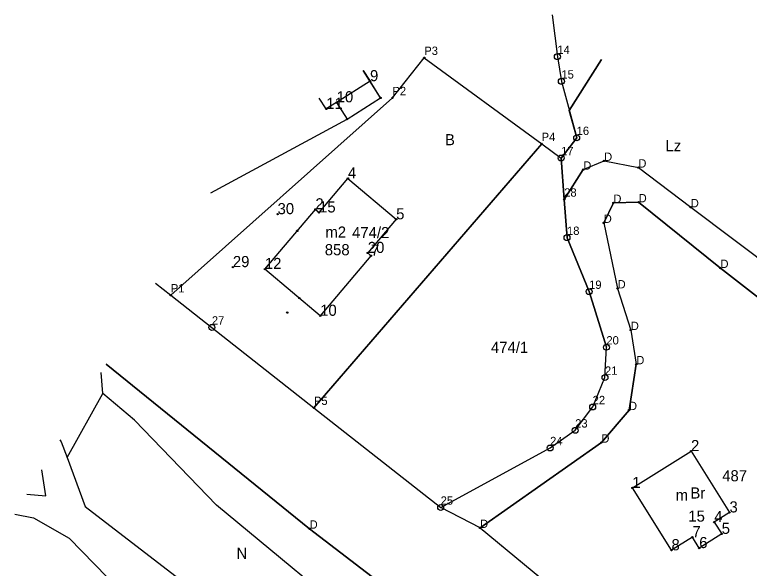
# Model space of a CAD drawing. Extents: x 7465393 to 7466459, y 5491258 to 5492404.
# Drawn here: x 7465422.8 to 7465521.9, y 5492329.6 to 5492404.3 of the extents above; entities that cross this region are included whole.
import ezdxf

# ---------------------------------------------------------------- set-up
doc = ezdxf.new("R2010")
doc.units = 0
for name, color, linetype in [('202-punkt graniczny', 7, 'Continuous'), ('202-punkt graniczny-Atr103', 7, 'Continuous'), ('203-punkt graniczny', 7, 'Continuous'), ('203-punkt graniczny-Atr103', 7, 'Continuous'), ('210-oznaczenie konturu użytku gruntowego', 7, 'Continuous'), ('211-numer działki ewidencyjnej', 7, 'Continuous'), ('217-kontur klasyfikacyjny', 7, 'Continuous'), ('218-kontur użytku gruntowego', 7, 'Continuous'), ('219-działka ewidencyjna', 7, 'Continuous'), ('312-budynek ewidencyjny', 7, 'Continuous'), ('312-oznaczenie budynku ewidencyjnego', 7, 'Continuous'), ('312-oznaczenie budynku ewidencyjnego-Atr117', 7, 'Continuous'), ('inny obiekt trwale związany z budynkiem (powierzchnia)', 7, 'Continuous'), ('Punkt budynku', 7, 'Continuous'), ('Punkt budynku-Atr103', 7, 'Continuous'), ('Punkt budynku-Atr104', 7, 'Continuous')]:
    doc.layers.add(name, color=color, linetype=linetype)

# ---------------------------------------------------------------- blocks, each defined once
blk = doc.blocks.new('203')
blk.add_circle((0, 0), 0.09)
blk = doc.blocks.new('202')
blk.add_circle((0, 0), 0.4)
blk = doc.blocks.new('PUNKTBUD')
blk.add_circle((0, 0), 0.09)

msp = doc.modelspace()

# ---------------------------------------------------------------- linework, layer by layer
at = {"layer": '217-kontur klasyfikacyjny'}
for points in [[(7465473.77, 5492393.05), (7465478.06, 5492398.48)], [(7465478.06, 5492398.48), (7465493.89, 5492386.86)], [(7465497.62, 5492391.35), (7465501.953, 5492398.257)], [(7465443.87, 5492366.44), (7465473.77, 5492393.05)], [(7465498.61, 5492387.68), (7465497.62, 5492391.35)], [(7465496.51, 5492384.95), (7465498.61, 5492387.68)], [(7465493.89, 5492386.86), (7465463.18, 5492351.26)], [(7465496.93, 5492379.36), (7465496.51, 5492384.95)], [(7465497.31, 5492374.2), (7465496.93, 5492379.36)], [(7465503.56, 5492378.89), (7465502.26, 5492376.2)], [(7465506.97, 5492378.97), (7465503.56, 5492378.89)], [(7465518, 5492370.11), (7465506.97, 5492378.97)], [(7465502.26, 5492376.2), (7465504.13, 5492367.35)], [(7465500.29, 5492366.92), (7465497.31, 5492374.2)], [(7465529.32, 5492361.27), (7465518, 5492370.11)], [(7465441.821, 5492368.048), (7465443.87, 5492366.44)], [(7465504.13, 5492367.35), (7465505.91, 5492361.74)], [(7465502.62, 5492359.42), (7465500.29, 5492366.92)], [(7465505.91, 5492361.74), (7465506.65, 5492357.12)], [(7465502.43, 5492355.33), (7465502.62, 5492359.42)], [(7465506.65, 5492357.12), (7465505.67, 5492350.94)], [(7465500.77, 5492351.36), (7465502.43, 5492355.33)], [(7465498.41, 5492348.21), (7465500.77, 5492351.36)], [(7465463.18, 5492351.26), (7465480.27, 5492337.8)], [(7465505.67, 5492350.94), (7465501.94, 5492346.55)], [(7465495.03, 5492345.83), (7465498.41, 5492348.21)], [(7465501.94, 5492346.55), (7465485.58, 5492335.04)], [(7465480.27, 5492337.8), (7465495.03, 5492345.83)], [(7465485.58, 5492335.04), (7465523.76, 5492303.5)]]:
    msp.add_lwpolyline(points, dxfattribs=at)
at = {"layer": '218-kontur użytku gruntowego'}
for points in [[(7465473.77, 5492393.05), (7465478.06, 5492398.48)], [(7465478.06, 5492398.48), (7465493.89, 5492386.86)], [(7465501.953, 5492398.257), (7465497.62, 5492391.35)], [(7465472.17, 5492393.07), (7465469.822, 5492396.777)], [(7465443.87, 5492366.44), (7465473.77, 5492393.05)], [(7465467.66, 5492390.21), (7465472.17, 5492393.07)], [(7465497.62, 5492391.35), (7465498.61, 5492387.68)], [(7465449.254, 5492380.23), (7465467.66, 5492390.21)], [(7465498.61, 5492387.68), (7465496.51, 5492384.95)], [(7465493.89, 5492386.86), (7465463.18, 5492351.26)], [(7465496.51, 5492384.95), (7465496.93, 5492379.36)], [(7465499.5, 5492383.38), (7465502.31, 5492384.56)], [(7465502.31, 5492384.56), (7465506.93, 5492383.66)], [(7465496.93, 5492379.36), (7465499.5, 5492383.38)], [(7465506.93, 5492383.66), (7465514, 5492378.3)], [(7465497.31, 5492374.2), (7465496.93, 5492379.36)], [(7465503.56, 5492378.89), (7465502.26, 5492376.2)], [(7465506.97, 5492378.97), (7465503.56, 5492378.89)], [(7465518, 5492370.11), (7465506.97, 5492378.97)], [(7465514, 5492378.3), (7465525.79, 5492369.48)], [(7465502.26, 5492376.2), (7465504.13, 5492367.35)], [(7465500.29, 5492366.92), (7465497.31, 5492374.2)], [(7465529.32, 5492361.27), (7465518, 5492370.11)], [(7465441.821, 5492368.048), (7465443.87, 5492366.44)], [(7465504.13, 5492367.35), (7465505.91, 5492361.74)], [(7465443.87, 5492366.44), (7465449.41, 5492362.1)], [(7465502.62, 5492359.42), (7465500.29, 5492366.92)], [(7465449.41, 5492362.1), (7465463.18, 5492351.26)], [(7465505.91, 5492361.74), (7465506.65, 5492357.12)], [(7465502.43, 5492355.33), (7465502.62, 5492359.42)], [(7465462.59, 5492334.94), (7465435.166, 5492357.141)], [(7465506.65, 5492357.12), (7465505.67, 5492350.94)], [(7465434.71, 5492353.16), (7465434.482, 5492356.021)], [(7465500.77, 5492351.36), (7465502.43, 5492355.33)], [(7465429.89, 5492344.53), (7465434.71, 5492353.16)], [(7465438.97, 5492349.58), (7465434.71, 5492353.16)], [(7465498.41, 5492348.21), (7465500.77, 5492351.36)], [(7465463.18, 5492351.26), (7465480.27, 5492337.8)], [(7465505.67, 5492350.94), (7465501.94, 5492346.55)], [(7465450.05, 5492338.11), (7465438.97, 5492349.58)], [(7465495.03, 5492345.83), (7465498.41, 5492348.21)], [(7465428.926, 5492346.915), (7465429.1, 5492346.66)], [(7465429.1, 5492346.66), (7465429.89, 5492344.53)], [(7465501.94, 5492346.55), (7465485.58, 5492335.04)], [(7465480.27, 5492337.8), (7465495.03, 5492345.83)], [(7465506.12, 5492340.43), (7465514.03, 5492345.4)], [(7465514.03, 5492345.4), (7465519.22, 5492337.13)], [(7465429.89, 5492344.53), (7465432.33, 5492337.92)], [(7465427.02, 5492339.39), (7465426.465, 5492342.882)], [(7465424.47, 5492339.612), (7465427.02, 5492339.39)], [(7465511.4, 5492332.03), (7465506.12, 5492340.43)], [(7465432.33, 5492337.92), (7465445.57, 5492327.74)], [(7465471.73, 5492320.14), (7465450.05, 5492338.11)], [(7465422.817, 5492336.903), (7465425.34, 5492336.41)], [(7465519.22, 5492337.13), (7465517.16, 5492335.83)], [(7465425.34, 5492336.41), (7465430.17, 5492333.65)], [(7465517.16, 5492335.83), (7465518.17, 5492334.24)], [(7465494.69, 5492310.3), (7465462.59, 5492334.94)], [(7465485.58, 5492335.04), (7465501.21, 5492322.13)], [(7465430.17, 5492333.65), (7465442.09, 5492321.44)], [(7465514.22, 5492333.79), (7465511.4, 5492332.03)], [(7465515.14, 5492332.32), (7465514.22, 5492333.79)], [(7465518.17, 5492334.24), (7465515.14, 5492332.32)]]:
    msp.add_lwpolyline(points, dxfattribs=at)
at = {"layer": '219-działka ewidencyjna'}
for points in [[(7465495.284, 5492404.286), (7465496.01, 5492398.62)], [(7465473.77, 5492393.05), (7465478.06, 5492398.48)], [(7465478.06, 5492398.48), (7465493.89, 5492386.86)], [(7465496.01, 5492398.62), (7465496.55, 5492395.29)], [(7465496.55, 5492395.29), (7465498.61, 5492387.68)], [(7465443.87, 5492366.44), (7465473.77, 5492393.05)], [(7465496.51, 5492384.95), (7465498.61, 5492387.68)], [(7465463.18, 5492351.26), (7465493.89, 5492386.86)], [(7465493.89, 5492386.86), (7465496.51, 5492384.95)], [(7465496.51, 5492384.95), (7465496.93, 5492379.36)], [(7465499.5, 5492383.38), (7465502.31, 5492384.56)], [(7465502.31, 5492384.56), (7465506.93, 5492383.66)], [(7465499.5, 5492383.38), (7465496.93, 5492379.36)], [(7465506.93, 5492383.66), (7465514, 5492378.3)], [(7465496.93, 5492379.36), (7465497.31, 5492374.2)], [(7465502.26, 5492376.2), (7465503.56, 5492378.89)], [(7465503.56, 5492378.89), (7465506.97, 5492378.97)], [(7465506.97, 5492378.97), (7465518, 5492370.11)], [(7465514, 5492378.3), (7465525.79, 5492369.48)], [(7465502.26, 5492376.2), (7465504.13, 5492367.35)], [(7465497.31, 5492374.2), (7465500.29, 5492366.92)], [(7465518, 5492370.11), (7465529.32, 5492361.27)], [(7465441.821, 5492368.048), (7465443.87, 5492366.44)], [(7465504.13, 5492367.35), (7465505.91, 5492361.74)], [(7465443.87, 5492366.44), (7465449.41, 5492362.1)], [(7465500.29, 5492366.92), (7465502.62, 5492359.42)], [(7465449.41, 5492362.1), (7465463.18, 5492351.26)], [(7465505.91, 5492361.74), (7465506.65, 5492357.12)], [(7465502.43, 5492355.33), (7465502.62, 5492359.42)], [(7465435.167, 5492357.143), (7465462.59, 5492334.94)], [(7465505.67, 5492350.94), (7465506.65, 5492357.12)], [(7465500.77, 5492351.36), (7465502.43, 5492355.33)], [(7465498.41, 5492348.21), (7465500.77, 5492351.36)], [(7465463.18, 5492351.26), (7465480.27, 5492337.8)], [(7465501.94, 5492346.55), (7465505.67, 5492350.94)], [(7465495.03, 5492345.83), (7465498.41, 5492348.21)], [(7465485.58, 5492335.04), (7465501.94, 5492346.55)], [(7465480.27, 5492337.8), (7465495.03, 5492345.83)], [(7465485.58, 5492335.04), (7465480.27, 5492337.8)], [(7465462.59, 5492334.94), (7465494.69, 5492310.3)], [(7465485.58, 5492335.04), (7465523.76, 5492303.5)]]:
    msp.add_lwpolyline(points, dxfattribs=at)
at = {"layer": '312-budynek ewidencyjny'}
for points in [[(7465469.818, 5492396.775), (7465470.74, 5492395.31)], [(7465470.74, 5492395.31), (7465466.24, 5492392.46)], [(7465464.83, 5492391.57), (7465463.9, 5492393.039)], [(7465466.24, 5492392.46), (7465464.83, 5492391.57)], [(7465463.87, 5492377.6), (7465467.76, 5492382.2)], [(7465467.76, 5492382.2), (7465474.27, 5492376.68)], [(7465456.56, 5492369.97), (7465463.37, 5492378.02)], [(7465463.37, 5492378.02), (7465463.87, 5492377.6)], [(7465474.27, 5492376.68), (7465470.44, 5492372.14)], [(7465470.44, 5492372.14), (7465470.87, 5492371.77)], [(7465470.87, 5492371.77), (7465464.02, 5492363.66)], [(7465464.02, 5492363.66), (7465456.56, 5492369.97)], [(7465506.12, 5492340.43), (7465514.03, 5492345.4)], [(7465514.03, 5492345.4), (7465519.22, 5492337.13)], [(7465511.4, 5492332.03), (7465506.12, 5492340.43)], [(7465519.22, 5492337.13), (7465517.16, 5492335.83)], [(7465517.16, 5492335.83), (7465518.17, 5492334.24)], [(7465514.22, 5492333.79), (7465511.4, 5492332.03)], [(7465515.14, 5492332.32), (7465514.22, 5492333.79)], [(7465518.17, 5492334.24), (7465515.14, 5492332.32)]]:
    msp.add_lwpolyline(points, dxfattribs=at)
at = {"layer": 'inny obiekt trwale związany z budynkiem (powierzchnia)'}
msp.add_lwpolyline([(7465470.74, 5492395.31), (7465466.24, 5492392.46), (7465467.66, 5492390.21), (7465472.16, 5492393.06)], close=True, dxfattribs=at)

# ---------------------------------------------------------------- block references
at = {"layer": '202-punkt graniczny'}
for p in [(7465496.01, 5492398.62), (7465496.55, 5492395.29), (7465498.61, 5492387.68), (7465496.51, 5492384.95), (7465497.31, 5492374.2), (7465500.29, 5492366.92), (7465449.41, 5492362.1), (7465502.62, 5492359.42), (7465502.43, 5492355.33), (7465500.77, 5492351.36), (7465498.41, 5492348.21), (7465495.03, 5492345.83), (7465480.27, 5492337.8)]:
    msp.add_blockref('202', p, dxfattribs=at)
at = {"layer": '203-punkt graniczny'}
for p in [(7465478.06, 5492398.48), (7465473.77, 5492393.05), (7465493.89, 5492386.86), (7465502.31, 5492384.56), (7465499.5, 5492383.38), (7465506.93, 5492383.66), (7465496.93, 5492379.36), (7465503.56, 5492378.89), (7465506.97, 5492378.97), (7465514, 5492378.3), (7465502.26, 5492376.2), (7465518, 5492370.11), (7465504.13, 5492367.35), (7465443.87, 5492366.44), (7465505.91, 5492361.74), (7465506.65, 5492357.12), (7465463.18, 5492351.26), (7465505.67, 5492350.94), (7465501.94, 5492346.55), (7465462.59, 5492334.94), (7465485.58, 5492335.04)]:
    msp.add_blockref('203', p, dxfattribs=at)
at = {"layer": 'Punkt budynku'}
for p in [(7465470.74, 5492395.31), (7465472.16, 5492393.06), (7465466.24, 5492392.46), (7465464.83, 5492391.57), (7465467.66, 5492390.21), (7465467.76, 5492382.2), (7465463.37, 5492378.02), (7465458.27, 5492377.37), (7465463.87, 5492377.6), (7465474.27, 5492376.68), (7465460.92, 5492375.12), (7465470.44, 5492372.14), (7465470.87, 5492371.77), (7465452.24, 5492370.23), (7465456.56, 5492369.97), (7465461.21, 5492366.04), (7465459.57, 5492364.1), (7465464.02, 5492363.66), (7465514.03, 5492345.4), (7465506.12, 5492340.43), (7465519.22, 5492337.13), (7465517.16, 5492335.83), (7465514.22, 5492333.79), (7465518.17, 5492334.24), (7465511.4, 5492332.03), (7465515.14, 5492332.32)]:
    msp.add_blockref('PUNKTBUD', p, dxfattribs=at)

# ---------------------------------------------------------------- texts
at = {"layer": '202-punkt graniczny-Atr103'}
for s, p in [('14', (7465496.01, 5492398.995)), ('15', (7465496.55, 5492395.665)), ('16', (7465498.61, 5492388.055)), ('17', (7465496.51, 5492385.325)), ('18', (7465497.31, 5492374.575)), ('19', (7465500.29, 5492367.295)), ('27', (7465449.41, 5492362.475)), ('20', (7465502.62, 5492359.795)), ('21', (7465502.43, 5492355.705)), ('22', (7465500.77, 5492351.735)), ('23', (7465498.41, 5492348.585)), ('24', (7465495.03, 5492346.205)), ('25', (7465480.27, 5492338.175))]:
    msp.add_text(s, height=1.125, dxfattribs=at).set_placement(p)
at = {"layer": '203-punkt graniczny-Atr103'}
for s, p in [('P3', (7465478.06, 5492398.855)), ('P2', (7465473.77, 5492393.425)), ('P4', (7465493.89, 5492387.235)), ('D', (7465502.31, 5492384.56)), ('D', (7465499.5, 5492383.38)), ('D', (7465506.93, 5492383.66)), ('28', (7465496.93, 5492379.735)), ('D', (7465506.97, 5492378.97)), ('D', (7465503.56, 5492378.89)), ('D', (7465514, 5492378.3)), ('D', (7465502.26, 5492376.2)), ('D', (7465518, 5492370.11)), ('D', (7465504.13, 5492367.35)), ('P1', (7465443.87, 5492366.815)), ('D', (7465505.91, 5492361.74)), ('D', (7465506.65, 5492357.12)), ('P5', (7465463.18, 5492351.635)), ('D', (7465505.67, 5492350.94)), ('D', (7465501.94, 5492346.55)), ('D', (7465462.59, 5492334.94)), ('D', (7465485.58, 5492335.04))]:
    msp.add_text(s, height=1.125, dxfattribs=at).set_placement(p)
at = {"layer": '210-oznaczenie konturu użytku gruntowego'}
for s, p in [('B', (7465480.85, 5492386.67)), ('Lz', (7465510.59, 5492385.87)), ('Br', (7465513.95, 5492339.01)), ('N', (7465452.73, 5492330.86))]:
    msp.add_text(s, height=1.5, dxfattribs=at).set_placement(p)
at = {"layer": '211-numer działki ewidencyjnej'}
for s, p in [('474/2', (7465468.32, 5492374.14)), ('474/1', (7465487.05, 5492358.65)), ('487', (7465518.24, 5492341.33))]:
    msp.add_text(s, height=1.5, dxfattribs=at).set_placement(p)
at = {"layer": '312-oznaczenie budynku ewidencyjnego'}
for s, p in [('858', (7465464.64, 5492371.83)), ('15', (7465513.67, 5492335.89))]:
    msp.add_text(s, height=1.5, dxfattribs=at).set_placement(p)
at = {"layer": '312-oznaczenie budynku ewidencyjnego-Atr117'}
for s, p in [('m2', (7465464.726, 5492374.21)), ('m', (7465511.963, 5492338.72))]:
    msp.add_text(s, height=1.5, dxfattribs=at).set_placement(p)
at = {"layer": 'Punkt budynku-Atr103'}
for s, p in [('15', (7465463.87, 5492377.6)), ('20', (7465470.44, 5492372.14)), ('12', (7465456.56, 5492369.97)), ('10', (7465464.02, 5492363.66))]:
    msp.add_text(s, height=1.5, dxfattribs=at).set_placement(p)
at = {"layer": 'Punkt budynku-Atr104'}
for s, p in [('9', (7465470.74, 5492395.31)), ('10', (7465466.24, 5492392.46)), ('11', (7465464.83, 5492391.57)), ('4', (7465467.76, 5492382.2)), ('2', (7465463.37, 5492378.02)), ('30', (7465458.27, 5492377.37)), ('5', (7465474.27, 5492376.68)), ('7', (7465470.87, 5492371.77)), ('29', (7465452.24, 5492370.23)), ('2', (7465514.03, 5492345.4)), ('1', (7465506.12, 5492340.43)), ('3', (7465519.22, 5492337.13)), ('4', (7465517.16, 5492335.83)), ('5', (7465518.17, 5492334.24)), ('7', (7465514.22, 5492333.79)), ('8', (7465511.4, 5492332.03)), ('6', (7465515.14, 5492332.32))]:
    msp.add_text(s, height=1.5, dxfattribs=at).set_placement(p)

doc.saveas('drawing.dxf')
